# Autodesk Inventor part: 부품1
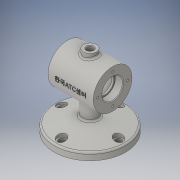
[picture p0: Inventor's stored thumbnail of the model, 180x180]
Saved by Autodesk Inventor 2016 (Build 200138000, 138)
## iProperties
Created: 2018-12
Part Number: 부품1
Material: Generic
Document SubType Name: Modeling
Designer: Administrator
Density: 1 g/cm^3
Appearance: Default
Author: Administrator
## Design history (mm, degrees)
sketch "스케치1"
  geometry: L1 (-35, 30)-(35, 30); L2 (35, 30)-(35, 0); L3 (35, 0)-(-35, 0); L4 (-35, 0)-(-35, 30); L5 (-35, 0)-(-23, 0); L6 (-23, 14)-(-23, 16); L7 (-23, 16)-(-35, 16); L8 (-35, 16)-(-35, 0); L9 (-23, 0)-(-20, 0); L10 (-20, 14)-(-23, 14); L11 (-20, 0)-(20, 0); L12 (20, 14)-(20, 25); L13 (20, 25)-(-20, 25); L14 (-20, 25)-(-20, 14); L15 (20, 0)-(23, 0); L16 (23, 14)-(20, 14); L17 (23, 0)-(35, 0); L18 (35, 0)-(35, 16); L19 (35, 16)-(23, 16); L20 (23, 16)-(23, 14); 2 further points
  constraints: 40 end point, 10 parallel, 6 horizontal, 4 perpendicular, 3 point on line, 2 collinear, 1 coincident, 1 midpoint
  dimensions: "d0" = 60 diameter of L1 L3; "d1" = 70 distance between parallel lines of L2 L4; "d2" = 32 diameter of L7 L3; "d3" = 28 diameter of L10 L3; "d4" = 50 diameter of L13 L3; "d6" = 40 distance of L12.end L13.end; "d8" = 12 distance of L6.end L7.end
revolve "회전1" sketch "스케치1" stored, may be unused: angle "d9" = 90 deg
fillet "모깎기1" dims "d10" = 3
fillet "모깎기2" dims "d11" = 0.3
node "작업 평면1"
sketch "스케치2"
  geometry: C1 r 10 at (0, 0); 1 further point
  constraints: 1 centre point, 1 coincident
  dimensions: "d13" = 20 diameter of C1
extrude "돌출1" join sketch "스케치2" stored distance "d14" = 10; taper "d15" = 0 deg
sketch "스케치3"
  geometry: C1 r 10 at (0, 0) reference; C2 r 5 at (0, 0); 1 further point
  constraints: 1 centre point, 1 coincident
  dimensions: "d16" = 10 diameter of C2
extrude "돌출2" cut sketch "스케치3" stored distance "d17" = 10; taper "d18" = 0 deg
fillet "모깎기3" dims "d19" = 3
sketch "스케치4"
  geometry: L1 (0, -75)-(-55, -75); L2 (-55, -75)-(-55, -64); L3 (-55, -64)-(-12, -52.478); L4 (0, -75)-(0, -30); L5 (-35, -30)-(35, -30) reference; L6 (-12, -52.478)-(0, -52.5); 1 further point
  constraints: 10 end point, 2 midpoint, 1 horizontal, 1 vertical
  dimensions: "d20" = 75 distance of point (0, 0) L1.start; "d23" = 110 diameter of L2 L4; "d24" = 11 distance of L1.end L2.end; "d26" = 75 deg angle of L2 L3; "d27" = 12 distance of L3.end L6.end
revolve "회전2" sketch "스케치4" stored, may be unused: angle "d28" = 90 deg
sketch "스케치5"
  geometry: C1 r 12 at (0, 0); 1 further point
  constraints: 1 centre point, 1 coincident
  dimensions: "d29" = 24 diameter of C1
extrude "돌출3" join sketch "스케치5" stored distance "d30" = 10; taper "d31" = 0 deg
fillet "모깎기4" dims "d32" = 3
sketch "스케치6"
  geometry: C1 r 4.5 at (0, -44); C2 r 4.5 at (-44, 0); C3 r 4.5 at (0, 44); C4 r 4.5 at (44, 0); A1 r 44 centre (0, 0) between (0, -44) and (-44, 0); 1 further point
  constraints: 5 centre point, 4 point on circle, 1 coincident
  dimensions: "d33" = 88 diameter of A1; "d34" = 9 diameter of C1; "d35" = 9 diameter of C2; "d36" = 9 diameter of C3; "d37" = 9 diameter of C4
extrude "돌출4" cut sketch "스케치6" stored distance "d38" = 10; taper "d39" = 0 deg
node "작업 평면2"
sketch "스케치7"
  geometry: C1 r 4.5 at (0, -44) reference; C2 r 7 at (0, -44); C3 r 4.5 at (44, 0) reference; C4 r 7 at (44, 0); C5 r 4.5 at (0, 44) reference; C6 r 7 at (0, 44); C7 r 4.5 at (-44, 0) reference; C8 r 7 at (-44, 0); 1 further point
  constraints: 4 centre point, 4 coincident
  dimensions: "d41" = 14 diameter of C2; "d42" = 14 diameter of C4; "d43" = 14 diameter of C6; "d44" = 14 diameter of C8
extrude "돌출5" cut sketch "스케치7" distance "d45" = 10; taper "d46" = 0 deg
chamfer "모따기1" distance "d47" = 1; stored, may be unused: second distance "d48" = 2, angle "d49" = 45 deg
sketch "스케치8"
  geometry: C1 r 30 at (0, 0) reference; A1 r 23 centre (0, 0) between (0, 23) and (-23, 0); 3 further points
  constraints: 4 point on circle, 1 centre point, 1 coincident
  dimensions: "d50" = 46 diameter of A1
hole "구멍1" sketch "스케치8" at (0, 23), (-23, 0), (0, -23), (23, 0) diameter "d51" = 3.242; stored, may be unused: countersink angle "d55" = 90 deg, drill point angle "d57" = 120 deg; dims "d52" = 8, "d53" = 4, "d54" = 2, "d56" = 10
node "작업 평면3"
sketch "스케치9"
  geometry: L1 (-35, -30)-(-35, 30) reference; 2 further points
  constraints: 1 other
  dimensions: "d59" = 35 distance from line of L1 point (0, 0); "d60" = 30 vertical distance of L1.end point (0, 0)
feature "엠보싱1" sketch "스케치9" dims "d0" = 60, "d1" = 70, "d2" = 32, "d3" = 28, "d4" = 50, "d6" = 40, "d8" = 12, "d10" = 3, "d61" = 0.5, "d62" = 0
node "솔리드1"
mirror "대칭1"
other parameters: "d12" = 37, "d58" = 36
